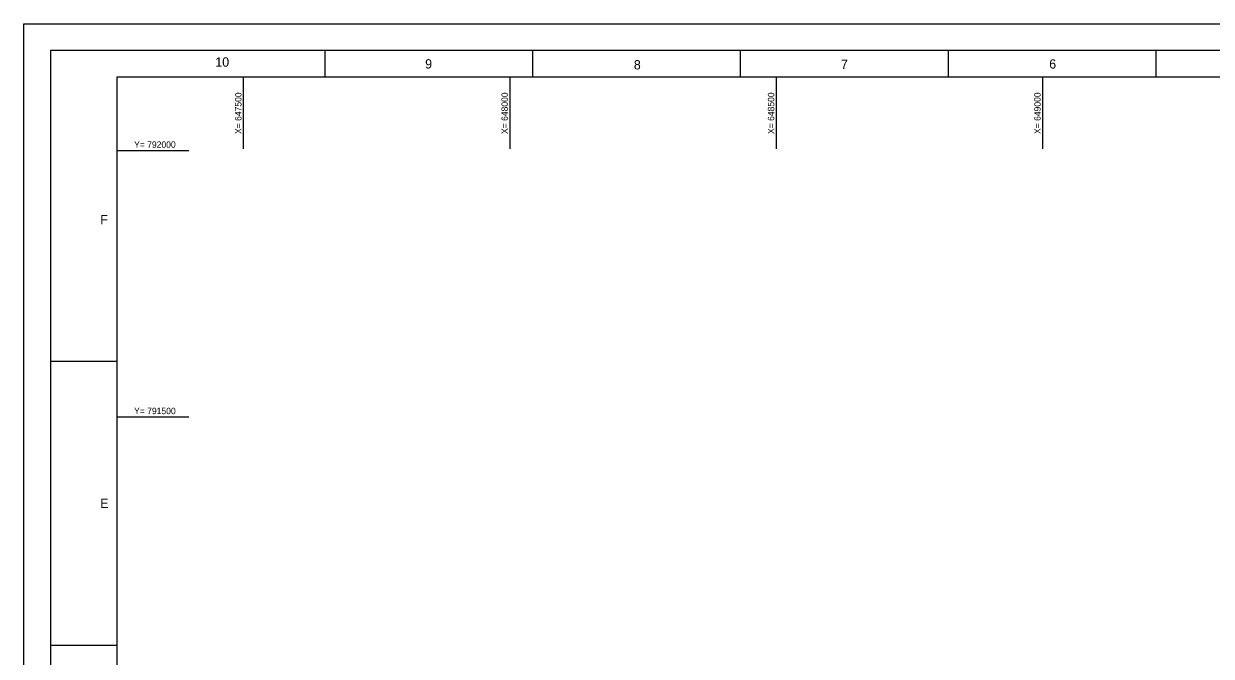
# Model space of a CAD drawing. Extents: x 647087 to 651487, y 788838 to 792238.
# Drawn here: x 647087 to 649316, y 791051 to 792238 of the extents above; entities that cross this region are included whole.
import ezdxf

# ---------------------------------------------------------------- set-up
doc = ezdxf.new("R2010")
doc.units = 0
for name, color, linetype in [('G-ANNO-NPLT', 7, 'Continuous'), ('G-ANNO-TTLB', 7, 'Continuous'), ('V-TOPO-COOR-STAT', 7, 'Continuous')]:
    doc.layers.add(name, color=color, linetype=linetype)

msp = doc.modelspace()

# ---------------------------------------------------------------- linework, layer by layer
at = {"layer": 'G-ANNO-NPLT'}
msp.add_lwpolyline([(647087.3, 792237.8), (651487.3, 792237.8), (651487.3, 788837.9), (647087.3, 788837.9)], close=True, dxfattribs=at)
msp.add_lwpolyline([(647087.3, 792187.8), (647087.3, 792237.8), (647137.3, 792237.8)], dxfattribs=at)
at = {"layer": 'G-ANNO-TTLB'}
for p, q in [((647652.3, 792187.8), (647652.3, 792137.8)), ((648042.3, 792187.8), (648042.3, 792137.8)), ((648042.3, 792187.8), (648042.3, 792137.8)), ((648432.3, 792187.8), (648432.3, 792137.8)), ((648822.3, 792187.8), (648822.3, 792137.8)), ((649212.3, 792187.8), (649212.3, 792137.8)), ((647137.3, 791604.3), (647262.3, 791604.3)), ((647137.3, 791071.1), (647262.3, 791071.1))]:
    msp.add_line(p, q, dxfattribs=at)
for points in [[(647137.3, 788887.9), (651437.3, 788887.9), (651437.3, 792187.8), (647137.3, 792187.8)], [(651387.3, 792137.8), (647262.3, 792137.8), (647262.3, 788937.9), (651387.3, 788937.9)]]:
    msp.add_lwpolyline(points, close=True, dxfattribs=at)
at = {"layer": 'V-TOPO-COOR-STAT'}
for p, q in [((647500, 792002.8), (647500, 792137.8)), ((648000, 792002.8), (648000, 792137.8)), ((648500, 792002.8), (648500, 792137.8)), ((649000, 792002.8), (649000, 792137.8)), ((647262.3, 792000), (647397.3, 792000)), ((647262.3, 791500), (647397.3, 791500))]:
    msp.add_line(p, q, dxfattribs=at)

# ---------------------------------------------------------------- texts
at = {"layer": 'G-ANNO-TTLB'}
for s, p in [('10', (647446.8, 792157.3)), ('9', (647840.7, 792153.8)), ('8', (648232.4, 792152.1)), ('7', (648621.1, 792152.9)), ('6', (649012.1, 792153.6)), ('F', (647230.8, 791861.5)), ('E', (647230.7, 791328.8))]:
    msp.add_text(s, height=17.5, dxfattribs=at).set_placement(p)
at = {"layer": 'V-TOPO-COOR-STAT'}
for s, p in [('X= 647500', (647496, 792030.9)), ('X= 648000', (647996, 792030.9)), ('X= 648500', (648496, 792030.9)), ('X= 649000', (648996, 792030.9))]:
    msp.add_text(s, height=12, rotation=90, dxfattribs=at).set_placement(p)
for s, p in [('Y= 792000', (647294.4, 792005)), ('Y= 791500', (647294.4, 791505))]:
    msp.add_text(s, height=12, dxfattribs=at).set_placement(p)

doc.saveas('drawing.dxf')
